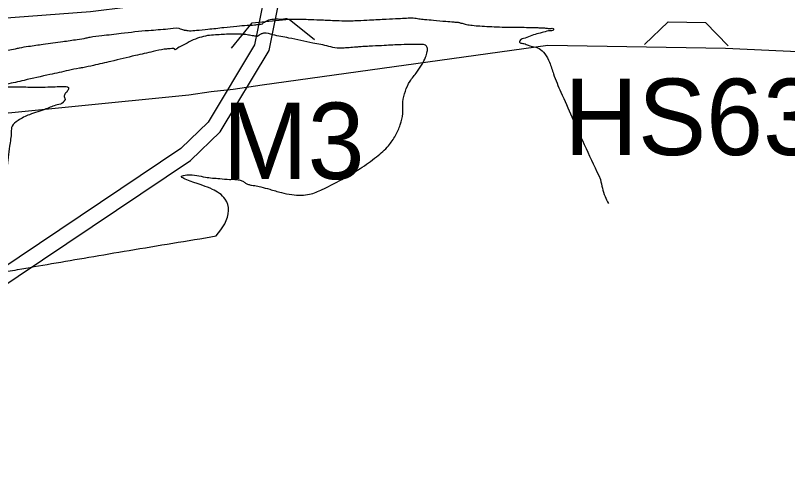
# Model space of a CAD drawing. Extents: x -478232 to -472707, y -1118753 to -1113967.
# Drawn here: x -477714.4 to -477613.4, y -1117465.6 to -1117404.3 of the extents above; entities that cross this region are included whole.
import ezdxf

# ---------------------------------------------------------------- set-up
doc = ezdxf.new("R2010")
doc.units = 0
for name, color, linetype in [('hospodářské sjezdy', 7, 'Continuous'), ('ObPÚ', 7, 'Continuous'), ('silnice', 7, 'Continuous'), ('TP_stavajicí_mosty', 7, 'Continuous'), ('vodní plochy', 7, 'Continuous'), ('Vrstevnice_vedlejsi', 7, 'Continuous')]:
    doc.layers.add(name, color=color, linetype=linetype)

msp = doc.modelspace()

# ---------------------------------------------------------------- linework, layer by layer
at = {"layer": 'hospodářské sjezdy'}
for p, q in [((-477632.071, -1117408.148), (-477629, -1117405.188)), ((-477629, -1117405.188), (-477624.116, -1117405.275)), ((-477624.116, -1117405.275), (-477621.152, -1117408.342))]:
    msp.add_line(p, q, dxfattribs=at)
at = {"layer": 'ObPÚ'}
msp.add_lwpolyline([(-477428.82, -1117417.33), (-477494.83, -1117414.18), (-477554.51, -1117411.78), (-477621.5, -1117408.68), (-477644.72, -1117408.28), (-477682.13, -1117413.46), (-477685.93, -1117414.02), (-477688.8, -1117414.36), (-477691.73, -1117414.77), (-477738.55, -1117419.44), (-477782.49, -1117430.5), (-477808.98, -1117437.26), (-477845.5, -1117449.81), (-477945.12, -1117479.46), (-478009.37, -1117499.81)], dxfattribs=at)
at = {"layer": 'silnice'}
msp.add_lwpolyline([(-478068.596, -1117511.329), (-477917.95, -1117462.993), (-477779.219, -1117418.245), (-477732.944, -1117407.585), (-477720.808, -1117405.048), (-477704.588, -1117403.835), (-477689.402, -1117401.926), (-477652.852, -1117401.691), (-477590.784, -1117403.37), (-477332.447, -1117414.279), (-477204.956, -1117416.797), (-477142.049, -1117416.797), (-477096.756, -1117410.083), (-477036.34, -1117397.174), (-476978.492, -1117379.033), (-476883.712, -1117344.626), (-476756.221, -1117298.47), (-476633.763, -1117254.832), (-476588.47, -1117242.245), (-476550.726, -1117234.692), (-476503.755, -1117230.496), (-476424.073, -1117228.817), (-476282.324, -1117220.425)], dxfattribs=at)
at = {"layer": 'TP_stavajicí_mosty'}
for p, q in [((-477686.134, -1117408.643), (-477683.444, -1117405.332)), ((-477683.444, -1117405.332), (-477678.585, -1117404.827)), ((-477678.585, -1117404.827), (-477675.271, -1117407.512))]:
    msp.add_line(p, q, dxfattribs=at)
at = {"layer": 'vodní plochy'}
for points in [[(-477707.831, -1117220.199), (-477703.482, -1117231.655), (-477698.355, -1117240.284), (-477689.395, -1117252.275), (-477687.972, -1117255.508), (-477686.896, -1117262.774), (-477686.896, -1117275.228), (-477685.95, -1117281.615), (-477670.19, -1117321.721), (-477667.007, -1117334.46), (-477667.007, -1117343.664), (-477669.39, -1117356.111), (-477673.373, -1117365.147), (-477678.776, -1117376.496), (-477681.809, -1117385.6), (-477681.541, -1117400.47), (-477683.107, -1117408.185), (-477689.177, -1117418.301), (-477692.755, -1117421.747), (-477721.795, -1117441.246), (-477735.582, -1117453.362), (-477747.829, -1117466.582)], [(-477773.189, -1117531.586), (-477767.822, -1117505.274), (-477763.455, -1117493.269), (-477752.743, -1117476.374), (-477746.295, -1117467.868), (-477734.184, -1117454.796), (-477720.573, -1117442.834), (-477691.495, -1117423.309), (-477687.599, -1117419.557), (-477681.215, -1117408.919), (-477679.537, -1117400.654), (-477679.803, -1117385.906), (-477676.918, -1117377.244), (-477671.555, -1117365.981), (-477667.468, -1117356.711), (-477665.007, -1117343.854), (-477665.007, -1117334.214), (-477668.282, -1117321.111), (-477683.577, -1117282.186)], [(-477773.189, -1117531.586), (-477767.822, -1117505.274), (-477763.455, -1117493.269), (-477752.743, -1117476.374), (-477746.295, -1117467.868), (-477734.184, -1117454.796), (-477720.573, -1117442.834), (-477691.495, -1117423.309), (-477687.599, -1117419.557), (-477681.215, -1117408.919), (-477679.537, -1117400.654), (-477679.803, -1117385.906), (-477676.918, -1117377.244), (-477671.555, -1117365.981), (-477667.468, -1117356.711), (-477665.007, -1117343.854), (-477665.007, -1117334.214), (-477668.282, -1117321.111), (-477683.577, -1117282.186)], [(-477667.007, -1117334.46), (-477667.007, -1117343.664), (-477669.39, -1117356.111), (-477673.373, -1117365.147), (-477678.776, -1117376.496), (-477681.809, -1117385.6), (-477681.541, -1117400.47), (-477683.107, -1117408.185), (-477689.177, -1117418.301), (-477692.755, -1117421.747), (-477721.795, -1117441.246), (-477735.582, -1117453.362), (-477747.829, -1117466.582), (-477754.387, -1117475.232), (-477765.261, -1117492.381), (-477769.752, -1117504.73), (-477775.149, -1117531.186)]]:
    msp.add_lwpolyline(points, dxfattribs=at)
at = {"layer": 'Vrstevnice_vedlejsi'}
for points in [[(-477670.605, -1117405.069), (-477670.42, -1117405.054), (-477669.569, -1117405.008), (-477668.052, -1117404.93), (-477665.87, -1117404.82), (-477664.263, -1117404.739), (-477663.229, -1117404.687), (-477662.77, -1117404.664), (-477662.351, -1117404.67), (-477661.971, -1117404.705), (-477661.63, -1117404.769), (-477660.869, -1117404.857), (-477659.688, -1117404.968), (-477658.087, -1117405.103), (-477657.02, -1117405.192), (-477656.486, -1117405.237), (-477656.485, -1117405.237), (-477656.304, -1117405.284), (-477655.941, -1117405.377), (-477655.397, -1117405.516), (-477654.626, -1117405.633), (-477653.628, -1117405.726), (-477652.401, -1117405.796), (-477651.078, -1117405.847), (-477649.657, -1117405.88), (-477648.14, -1117405.894), (-477646.935, -1117405.914), (-477646.043, -1117405.939), (-477645.464, -1117405.97), (-477644.928, -1117406.009), (-477644.435, -1117406.058), (-477643.985, -1117406.115), (-477643.977, -1117406.213), (-477644.411, -1117406.352), (-477645.287, -1117406.531), (-477646.167, -1117406.761), (-477647.052, -1117407.044), (-477647.941, -1117407.379), (-477648.398, -1117407.649), (-477648.423, -1117407.855), (-477648.014, -1117407.997), (-477647.457, -1117408.181), (-477646.749, -1117408.406), (-477645.891, -1117408.674), (-477645.146, -1117409.362), (-477644.514, -1117410.473), (-477643.994, -1117412.004), (-477643.021, -1117414.39), (-477641.596, -1117417.631), (-477637.841, -1117425.821)], [(-477714.4, -1117408.695), (-477713.88, -1117408.578), (-477712.673, -1117408.383), (-477710.778, -1117408.11), (-477708.197, -1117407.759), (-477706.312, -1117407.486), (-477705.124, -1117407.291), (-477704.632, -1117407.174), (-477703.11, -1117406.969), (-477700.556, -1117406.677), (-477696.971, -1117406.297), (-477694.461, -1117406.081), (-477693.026, -1117406.03), (-477692.665, -1117406.142), (-477692.424, -1117406.219), (-477692.302, -1117406.259), (-477692.3, -1117406.263), (-477692.187, -1117406.278), (-477691.963, -1117406.303), (-477691.628, -1117406.339), (-477690.714, -1117406.286), (-477689.219, -1117406.145), (-477687.144, -1117405.916), (-477685.437, -1117405.745), (-477684.098, -1117405.632), (-477683.125, -1117405.577), (-477682.45, -1117405.507), (-477682.072, -1117405.423), (-477681.99, -1117405.325), (-477681.825, -1117405.211), (-477681.575, -1117405.081), (-477681.24, -1117404.935), (-477680.853, -1117404.842), (-477680.414, -1117404.802), (-477679.923, -1117404.814), (-477679.548, -1117404.813), (-477679.29, -1117404.8), (-477679.149, -1117404.774), (-477679.013, -1117404.765), (-477678.883, -1117404.774), (-477678.757, -1117404.801), (-477678.434, -1117404.819), (-477677.915, -1117404.828), (-477677.198, -1117404.829), (-477676.088, -1117404.858), (-477674.584, -1117404.915), (-477672.688, -1117405), (-477671.361, -1117405.051), (-477670.605, -1117405.069)], [(-477688.123, -1117433.202), (-477686.515, -1117429.862), (-477686.949, -1117428.387), (-477688.622, -1117427.107), (-477691.532, -1117426.022), (-477692.655, -1117425.393), (-477691.991, -1117425.222), (-477689.539, -1117425.508), (-477687.673, -1117425.698), (-477686.393, -1117425.793), (-477685.699, -1117425.792), (-477685.119, -1117425.872), (-477684.653, -1117426.034), (-477684.3, -1117426.276), (-477683.922, -1117426.453), (-477683.517, -1117426.562), (-477683.086, -1117426.605), (-477682.29, -1117426.781), (-477681.131, -1117427.09), (-477679.607, -1117427.532), (-477678.229, -1117427.788), (-477676.995, -1117427.857), (-477675.907, -1117427.741), (-477674.26, -1117427.121), (-477672.055, -1117425.998), (-477669.292, -1117424.371), (-477667.14, -1117422.837), (-477665.597, -1117421.396), (-477664.665, -1117420.047), (-477664.037, -1117418.642), (-477663.712, -1117417.18), (-477663.691, -1117415.663), (-477663.377, -1117414.253), (-477662.77, -1117412.951), (-477661.87, -1117411.756), (-477661.194, -1117410.712), (-477660.742, -1117409.818), (-477660.514, -1117409.074), (-477660.521, -1117408.548), (-477660.763, -1117408.24), (-477661.242, -1117408.149), (-477662.296, -1117408.126), (-477663.927, -1117408.171), (-477666.133, -1117408.283), (-477667.669, -1117408.361), (-477668.535, -1117408.405), (-477668.73, -1117408.414), (-477669.161, -1117408.445), (-477669.829, -1117408.497), (-477670.734, -1117408.57), (-477671.397, -1117408.615), (-477671.819, -1117408.634), (-477671.999, -1117408.626), (-477672.142, -1117408.621), (-477672.248, -1117408.618), (-477672.316, -1117408.618), (-477673.399, -1117408.398), (-477675.497, -1117407.957), (-477678.61, -1117407.297), (-477680.733, -1117406.865), (-477681.866, -1117406.663), (-477682.009, -1117406.69), (-477682.156, -1117406.735), (-477682.305, -1117406.8), (-477682.456, -1117406.883), (-477682.571, -1117406.955), (-477682.649, -1117407.014), (-477682.69, -1117407.061), (-477682.718, -1117407.092), (-477682.731, -1117407.108), (-477682.732, -1117407.108), (-477682.959, -1117407.07), (-477683.412, -1117406.995), (-477684.092, -1117406.883), (-477684.811, -1117406.813), (-477685.567, -1117406.784), (-477686.362, -1117406.796), (-477687.244, -1117406.835), (-477688.211, -1117406.9), (-477689.265, -1117406.991), (-477690.323, -1117407.246), (-477691.387, -1117407.666), (-477692.456, -1117408.25), (-477693.178, -1117408.625), (-477693.552, -1117408.792), (-477693.578, -1117408.749), (-477693.615, -1117408.715), (-477693.662, -1117408.688), (-477693.72, -1117408.67), (-477693.951, -1117408.679), (-477694.354, -1117408.713), (-477694.93, -1117408.774), (-477696.381, -1117409.069), (-477698.707, -1117409.598), (-477701.907, -1117410.36), (-477704.195, -1117410.889), (-477705.572, -1117411.185)], [(-477783.419, -1117450.824), (-477783.385, -1117443.847), (-477783.344, -1117437.193), (-477783.307, -1117433.697), (-477783.275, -1117433.361), (-477783.245, -1117433.129), (-477783.218, -1117433.001), (-477783.192, -1117432.977), (-477783.169, -1117432.951), (-477783.147, -1117432.922), (-477783.127, -1117432.89), (-477783.109, -1117432.856), (-477783.092, -1117432.82), (-477783.076, -1117432.783), (-477782.922, -1117432.552), (-477782.631, -1117432.129), (-477782.201, -1117431.512), (-477781.664, -1117430.783), (-477781.019, -1117429.941), (-477780.266, -1117428.987), (-477780.53, -1117428.456), (-477781.81, -1117428.35), (-477784.107, -1117428.667), (-477785.776, -1117428.888), (-477786.815, -1117429.013), (-477787.226, -1117429.04), (-477787.571, -1117429.053), (-477787.848, -1117429.051), (-477788.059, -1117429.033), (-477788.029, -1117428.944), (-477787.757, -1117428.782), (-477787.246, -1117428.548), (-477786.835, -1117428.368), (-477786.525, -1117428.243), (-477786.317, -1117428.173), (-477784.916, -1117427.721), (-477782.322, -1117426.887), (-477778.536, -1117425.672), (-477775.697, -1117424.742), (-477773.807, -1117424.097), (-477772.864, -1117423.738), (-477771.744, -1117423.335), (-477770.448, -1117422.886), (-477768.974, -1117422.392), (-477767.095, -1117421.76), (-477764.81, -1117420.99), (-477762.118, -1117420.08), (-477759.905, -1117419.343), (-477758.17, -1117418.777), (-477756.914, -1117418.384), (-477755.618, -1117418.008), (-477754.281, -1117417.651), (-477752.904, -1117417.311), (-477751.327, -1117416.903), (-477749.55, -1117416.426), (-477747.572, -1117415.881), (-477745.496, -1117415.333), (-477743.321, -1117414.782), (-477741.048, -1117414.229), (-477739.073, -1117413.753), (-477737.397, -1117413.355), (-477736.019, -1117413.035), (-477734.443, -1117412.684), (-477732.669, -1117412.301), (-477730.696, -1117411.887), (-477728.742, -1117411.469), (-477726.807, -1117411.047), (-477724.891, -1117410.622), (-477723.376, -1117410.303), (-477722.261, -1117410.09), (-477721.548, -1117409.983), (-477720.415, -1117409.793), (-477718.862, -1117409.521), (-477716.891, -1117409.167), (-477715.404, -1117408.891), (-477714.4, -1117408.695)], [(-477705.572, -1117411.185), (-477706.038, -1117411.248), (-477707.477, -1117411.545), (-477709.889, -1117412.075), (-477713.274, -1117412.839), (-477715.534, -1117413.349), (-477716.668, -1117413.604), (-477716.676, -1117413.606), (-477716.75, -1117413.617), (-477716.89, -1117413.638), (-477717.096, -1117413.669), (-477717.175, -1117413.687), (-477717.126, -1117413.691), (-477716.95, -1117413.682), (-477716.808, -1117413.675), (-477716.7, -1117413.668), (-477716.626, -1117413.663), (-477715.907, -1117413.669), (-477714.541, -1117413.685), (-477712.53, -1117413.712), (-477710.845, -1117413.713), (-477709.486, -1117413.686), (-477708.454, -1117413.633), (-477707.773, -1117413.662), (-477707.444, -1117413.774), (-477707.467, -1117413.968), (-477707.548, -1117414.166), (-477707.687, -1117414.367), (-477707.884, -1117414.573), (-477707.993, -1117414.774), (-477708.012, -1117414.971), (-477707.943, -1117415.164), (-477707.915, -1117415.314), (-477707.929, -1117415.421), (-477707.985, -1117415.486), (-477708.043, -1117415.56), (-477708.103, -1117415.644), (-477708.166, -1117415.738), (-477708.933, -1117416.051), (-477710.403, -1117416.584), (-477712.577, -1117417.335), (-477714.059, -1117418.09), (-477714.848, -1117418.847), (-477714.944, -1117419.608), (-477715.161, -1117421.452), (-477715.5, -1117424.382), (-477715.959, -1117428.397), (-477716.339, -1117431.126), (-477716.641, -1117432.572), (-477716.863, -1117432.733), (-477716.978, -1117433.03), (-477716.984, -1117433.465), (-477716.882, -1117434.036), (-477717.013, -1117434.837), (-477717.376, -1117435.868), (-477717.971, -1117437.128), (-477716.886, -1117437.707), (-477714.122, -1117437.606), (-477709.678, -1117436.825), (-477704.814, -1117435.988), (-477699.53, -1117435.096), (-477688.123, -1117433.202)], [(-477637.841, -1117425.821), (-477637.256, -1117428.024), (-477636.819, -1117428.94)]]:
    msp.add_spline(points, degree=3, dxfattribs=at)

# ---------------------------------------------------------------- texts
at = {"layer": 'hospodářské sjezdy'}
msp.add_text('HS63', height=10, rotation=359.99999, dxfattribs=at).set_placement((-477642.594, -1117422.613))
at = {"layer": 'TP_stavajicí_mosty'}
msp.add_text('M3', height=10, rotation=359.99999, dxfattribs=at).set_placement((-477687.303, -1117425.751))

doc.saveas('drawing.dxf')
